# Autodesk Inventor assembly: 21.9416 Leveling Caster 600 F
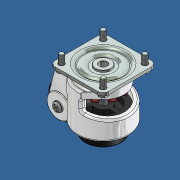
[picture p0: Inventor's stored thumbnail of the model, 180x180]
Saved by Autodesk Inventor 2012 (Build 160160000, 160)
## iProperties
Created: 2015-01
Part Number: 21.9416 Leveling Caster 600 F
Document SubType Name: Assembly
Designer: Admin
Author: Admin
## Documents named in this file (5)
- C:\Andys Backup Data\ANDY'S INVENTOR\INVENTOR LIBRARIES\PARTS LIBRARY\FEET WHEELS FLOOR FASTENING SUPPORTS\21.9416 Leveling Caster 600 F.iam
- C:\Andys Backup Data\ANDY'S INVENTOR\INVENTOR LIBRARIES\PARTS LIBRARY\FEET WHEELS FLOOR FASTENING SUPPORTS\SUBCOMPONENTS\21.9416 Leveling Caster 600 F Body.ipt
- C:\Andys Backup Data\ANDY'S INVENTOR\INVENTOR LIBRARIES\PARTS LIBRARY\FEET WHEELS FLOOR FASTENING SUPPORTS\SUBCOMPONENTS\21.9416 Leveling Caster 600 F Wheel.ipt
- C:\Andys Backup Data\ANDY'S INVENTOR\INVENTOR LIBRARIES\PARTS LIBRARY\FASTENING ELEMENTS\SCREWS OTHER\HEX BOLT M8X20.ipt
- C:\Andys Backup Data\ANDY'S INVENTOR\INVENTOR LIBRARIES\PARTS LIBRARY\FASTENING ELEMENTS\NUTS\21.1526 M8 HEX NUT.ipt
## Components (10 placed, 4 different names)
1. 21.9416 Leveling Caster 600 F Body:1 — Mate:1, Mate:2, Insert:1, Insert:2, Insert:3, Insert:4
2. 21.9416 Leveling Caster 600 F Wheel:1 — Mate:1, Mate:2
3. HEX BOLT M8X20 DIN 931:1 — Insert:3, Insert:7
4. HEX BOLT M8X20 DIN 931:2 — Insert:4, Insert:6
5. HEX BOLT M8X20 DIN 931:3 — Insert:2, Insert:8
6. HEX BOLT M8X20 DIN 931:4 — Insert:1, Insert:5
7. 21.1526 M8 HEX NUT:1 — Insert:7
8. 21.1526 M8 HEX NUT:2 — Insert:8
9. 21.1526 M8 HEX NUT:3 — Insert:6
10. 21.1526 M8 HEX NUT:4 — Insert:5
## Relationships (10: Insert 8, Mate 2)
- Mate:1: 21.9416 Leveling Caster 600 F Body:1 ↔ 21.9416 Leveling Caster 600 F Wheel:1
- Mate:2: 21.9416 Leveling Caster 600 F Body:1 ↔ 21.9416 Leveling Caster 600 F Wheel:1
- Insert:1: 21.9416 Leveling Caster 600 F Body:1 ↔ HEX BOLT M8X20 DIN 931:4
- Insert:2: 21.9416 Leveling Caster 600 F Body:1 ↔ HEX BOLT M8X20 DIN 931:3
- Insert:3: 21.9416 Leveling Caster 600 F Body:1 ↔ HEX BOLT M8X20 DIN 931:1
- Insert:4: 21.9416 Leveling Caster 600 F Body:1 ↔ HEX BOLT M8X20 DIN 931:2
- Insert:5: HEX BOLT M8X20 DIN 931:4 ↔ 21.1526 M8 HEX NUT:4
- Insert:6: HEX BOLT M8X20 DIN 931:2 ↔ 21.1526 M8 HEX NUT:3
- Insert:7: HEX BOLT M8X20 DIN 931:1 ↔ 21.1526 M8 HEX NUT:1
- Insert:8: HEX BOLT M8X20 DIN 931:3 ↔ 21.1526 M8 HEX NUT:2
